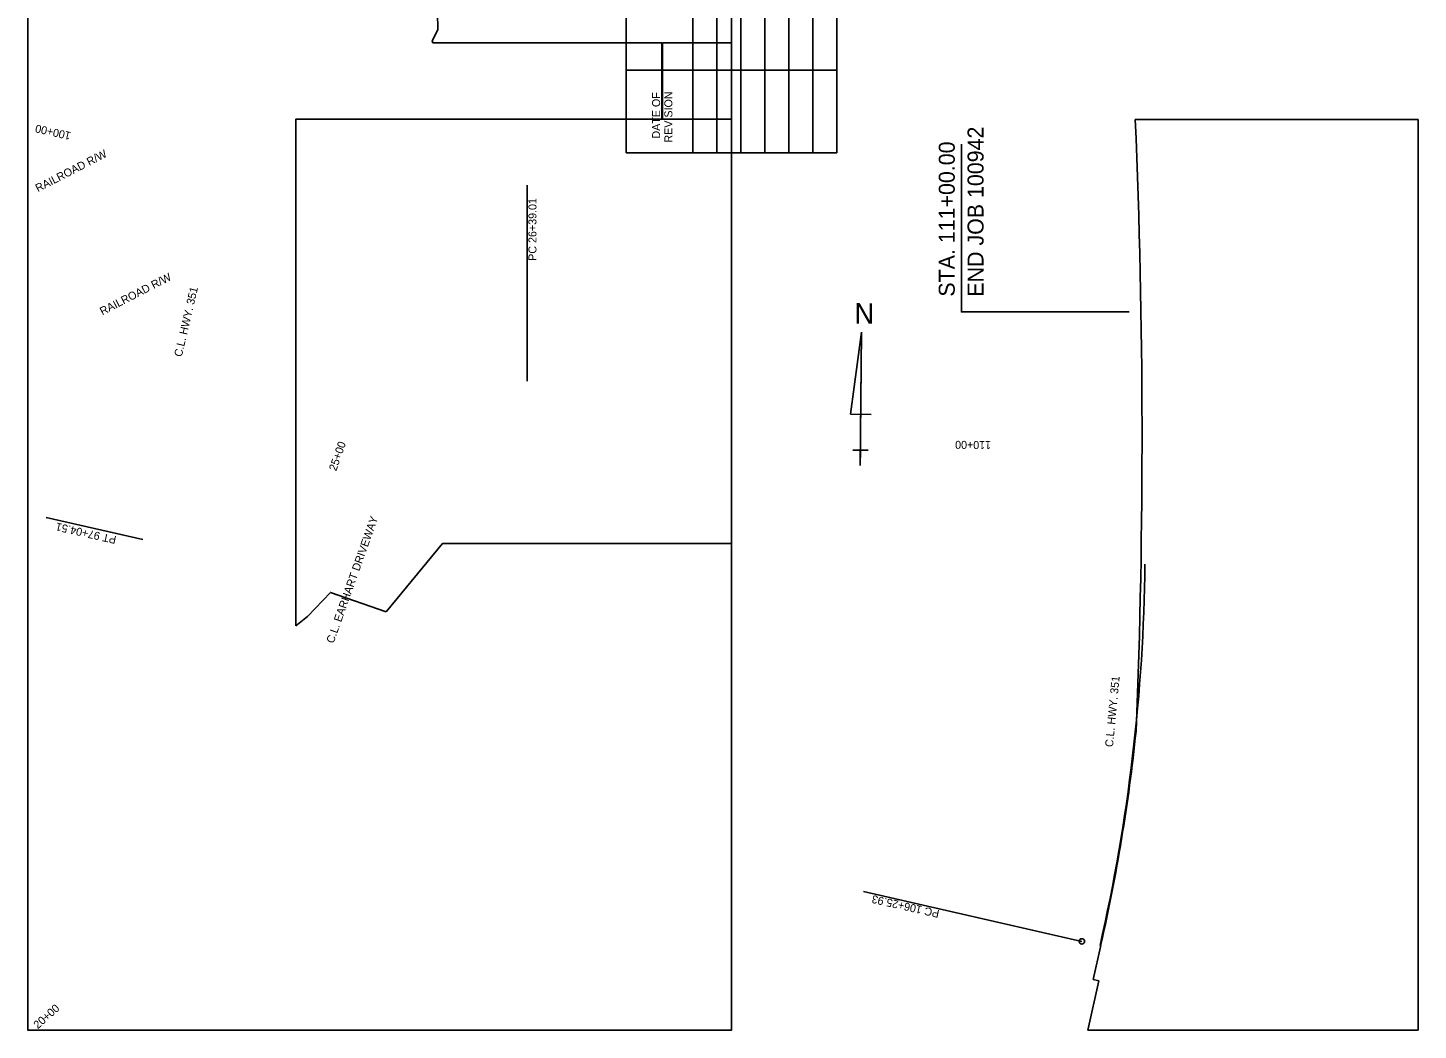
# Model space of a CAD drawing. Extents: x 1712161 to 1713203, y 549259 to 550855.
# Drawn here: x 1712161 to 1713203, y 549259 to 550011 of the extents above; entities that cross this region are included whole.
import ezdxf

# ---------------------------------------------------------------- set-up
doc = ezdxf.new("R2010")
doc.units = 0
for name, color, linetype in [('R_Erosion_STG 2', 7, 'Continuous'), ('R_Horz Alg', 7, 'Continuous'), ('R_Horz Alg Annot', 7, 'Continuous'), ('R_MOT', 7, 'Continuous')]:
    doc.layers.add(name, color=color, linetype=linetype)

msp = doc.modelspace()

# ---------------------------------------------------------------- linework, layer by layer
at = {"layer": 'R_Erosion_STG 2'}
for p, q in [((1712464.3, 549999.7), (1712635.8, 549999.7)), ((1712464.3, 549999.7), (1712635.8, 549999.7)), ((1712635.8, 549999.7), (1712635.8, 549942.6)), ((1712635.8, 549999.7), (1712635.8, 549942.6)), ((1712636.3, 549942.6), (1712636.3, 549999.7)), ((1712636.3, 549942.6), (1712636.3, 549999.7)), ((1712361.6, 549942.6), (1712635.8, 549942.6)), ((1712990.8, 549942.3), (1713202.9, 549942.3)), ((1712990.8, 549942.3), (1713202.9, 549942.3)), ((1712429.3, 549572.9), (1712471.5, 549624.2)), ((1712429.3, 549572.9), (1712471.5, 549624.2)), ((1712429.3, 549572.9), (1712471.5, 549624.2)), ((1712991.5, 549483.4), (1712991.5, 549483.4)), ((1712991.5, 549483.4), (1712991.5, 549483.4)), ((1712959.2, 549297.3), (1712964.9, 549322.6)), ((1712959.2, 549297.3), (1712964.9, 549322.6)), ((1712955.2, 549259.2), (1712963.6, 549296.3)), ((1712955.2, 549259.2), (1712963.6, 549296.3)), ((1712963.6, 549296.3), (1712959.2, 549297.3)), ((1712963.6, 549296.3), (1712959.2, 549297.3))]:
    msp.add_line(p, q, dxfattribs=at)
for points in [[(1712361.5, 550854.5), (1712688.2, 550854.5), (1712688.2, 549259.2), (1712160.6, 549259.2), (1712160.6, 550443.2), (1712210, 550443.2), (1712210, 550620.8), (1712227.8, 550620.8), (1712227.8, 550639), (1712224.6, 550639), (1712224.6, 550716.7)], [(1712688.2, 549999.7), (1712688.2, 550854.5), (1712495.7, 550854.5)], [(1712688.2, 549999.7), (1712688.2, 550854.5), (1712495.7, 550854.5)], [(1712467.8, 550022.6), (1712468.1, 550009.5), (1712463.8, 550001.4), (1712464.3, 549999.7)], [(1712467.8, 550022.6), (1712468.1, 550009.5), (1712463.8, 550001.4), (1712464.3, 549999.7)], [(1712636.3, 549999.7), (1712688.2, 549999.7)], [(1712636.3, 549999.7), (1712688.2, 549999.7)], [(1712635.8, 549942.6), (1712361.6, 549942.6), (1712361.6, 549562.6)], [(1712635.8, 549942.6), (1712361.6, 549942.6), (1712361.6, 549562.6)], [(1712635.8, 549942.6), (1712361.6, 549942.6), (1712361.6, 549562.6)], [(1712688.2, 549942.6), (1712361.6, 549942.6)], [(1712688.2, 549942.6), (1712636.3, 549942.6)], [(1712688.2, 549942.6), (1712636.3, 549942.6)], [(1712688.2, 549624.2), (1712688.2, 549942.6)], [(1712688.2, 549624.2), (1712688.2, 549942.6)], [(1712688.2, 549624.2), (1712688.2, 549942.6)], [(1713202.9, 549942.3), (1713202.9, 549259.2), (1712955.2, 549259.2)], [(1713202.9, 549942.3), (1713202.9, 549259.2), (1712955.2, 549259.2)], [(1712471.5, 549624.2), (1712688.2, 549624.2)], [(1712471.5, 549624.2), (1712688.2, 549624.2)], [(1712471.5, 549624.2), (1712688.2, 549624.2)], [(1712361.6, 549562.6), (1712370.3, 549569.5), (1712387.4, 549587.5), (1712429.3, 549572.9)], [(1712361.6, 549562.6), (1712370.3, 549569.5), (1712387.4, 549587.5), (1712429.3, 549572.9)], [(1712361.6, 549562.6), (1712370.3, 549569.5), (1712387.4, 549587.5), (1712429.3, 549572.9)]]:
    msp.add_lwpolyline(points, dxfattribs=at)
for centre, radius, start, end in [((1707466.7, 549704.5), 5529.2, 357.7082, 2.4649), ((1707466.7, 549704.5), 5529.2, 357.7082, 2.4649), ((1711636.1, 549624.3), 1362.6, 347.2066, 354.0638), ((1711636.1, 549624.3), 1362.6, 347.2066, 354.0638)]:
    msp.add_arc(centre, radius, start, end, dxfattribs=at)
at = {"layer": 'R_Horz Alg'}
for p, q in [((1712785.7, 549782.7), (1712777.4, 549721.3)), ((1712784.6, 549682.7), (1712785.7, 549782.7)), ((1712785.7, 549782.7), (1712784.9, 549705.8)), ((1712777.4, 549721.3), (1712792.8, 549721.1)), ((1712784.6, 549682.7), (1712784.9, 549705.8)), ((1712784.8, 549694.3), (1712779, 549694.3)), ((1712779, 549694.3), (1712790.5, 549694.2)), ((1712784.6, 549682.7), (1712784.8, 549694.3))]:
    msp.add_line(p, q, dxfattribs=at)
at = {"layer": 'R_Horz Alg Annot'}
for p, q in [((1712609.2, 549917.3), (1712609.2, 550404.2)), ((1712659.2, 549917.3), (1712659.2, 550404.2)), ((1712677.2, 549917.3), (1712677.2, 550404.2)), ((1712695.2, 549917.3), (1712695.2, 550404.2)), ((1712713.2, 549917.3), (1712713.2, 550404.2)), ((1712731.2, 549917.3), (1712731.2, 550404.2)), ((1712749.2, 549917.3), (1712749.2, 550404.2)), ((1712767.2, 549917.3), (1712767.2, 550404.2)), ((1712609.2, 549979.2), (1712767.2, 549979.2)), ((1712609.2, 549917.3), (1712767.2, 549917.3)), ((1712688.2, 549259.2), (1712688.2, 549917.3))]:
    msp.add_line(p, q, dxfattribs=at)
for points in [[(1712986.3, 549798), (1712860.5, 549798), (1712860.5, 549923.8)], [(1712535, 549746.1), (1712535, 549893)], [(1712246.8, 549627.3), (1712174.3, 549643.7)], [(1712950.8, 549325.8), (1712787.2, 549363.2)]]:
    msp.add_lwpolyline(points, dxfattribs=at)
msp.add_circle((1712950.8, 549325.8), 2, dxfattribs=at)
at = {"layer": 'R_MOT'}
msp.add_arc((1711636.1, 549624.3), 1362.1, 347.2066, 359.3498, dxfattribs=at)

# ---------------------------------------------------------------- texts
at = {"layer": 'R_Horz Alg'}
msp.add_text('N', height=15.4, rotation=359.3683, dxfattribs=at).set_placement((1712780.2, 549789.2))
at = {"layer": 'R_Horz Alg Annot'}
for s, height, rotation, p in [('DATE OF', 6, 90, (1712634.6, 549928)), ('REVISION', 6, 90, (1712643.8, 549925)), ('100+00', 6, 167.2066, (1712193.3, 549932.7)), ('END JOB 100942', 12, 90, (1712877.1, 549809.4)), ('RAILROAD R/W', 6, 27.2066, (1712168.2, 549887.7)), ('STA. 111+00.00', 12, 90, (1712855.5, 549809.4)), ('PC 26+39.01', 6, 90, (1712541.9, 549836.3)), ('RAILROAD R/W', 6, 27.2066, (1712216.5, 549795.3)), ('C.L. HWY. 351', 6, 76.7828, (1712276, 549763.9)), ('25+00', 6, 70.7734, (1712391.8, 549678.2)), ('110+00', 6, 179.3498, (1712882.8, 549701)), ('PT 97+04.51', 6, 167.2066, (1712227.4, 549629.7)), ('C.L. EARHART DRIVEWAY', 6, 70.4957, (1712389.8, 549548.9)), ('C.L. HWY. 351', 6, 84.5388, (1712974.1, 549471.3)), ('PC 106+25.93', 6, 167.2066, (1712844.4, 549349.2)), ('20+00', 6, 41.6088, (1712168.1, 549259.8))]:
    msp.add_text(s, height=height, rotation=rotation, dxfattribs=at).set_placement(p)

doc.saveas('drawing.dxf')
